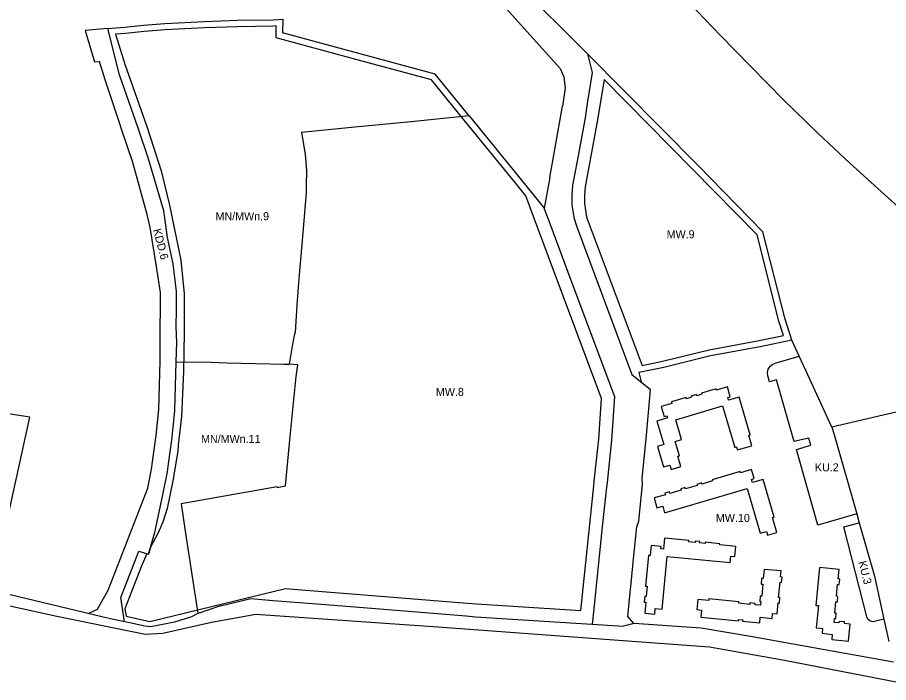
# Model space of a CAD drawing. Extents: x 7427074 to 7428708, y 5545888 to 5547145.
# Drawn here: x 7427887 to 7428431, y 5545888 to 5546303 of the extents above; entities that cross this region are included whole.
import ezdxf

# ---------------------------------------------------------------- set-up
doc = ezdxf.new("R2010")
doc.units = 0
for name, color, linetype in [('linie_rozgraniczajace', 7, 'Continuous'), ('linie_zabudowy_nieprzekraczalne', 7, 'Continuous'), ('linie_zabudowy_obowiazujace', 7, 'Continuous'), ('oznaczenia_przeznaczen', 7, 'Continuous')]:
    doc.layers.add(name, color=color, linetype=linetype)

msp = doc.modelspace()

# ---------------------------------------------------------------- linework, layer by layer
at = {"layer": 'linie_rozgraniczajace'}
for p, q in [((7428198.69, 5546324.88), (7428234.46, 5546289.38)), ((7428243.44, 5546280.38), (7428234.46, 5546289.38)), ((7428219.72, 5546203.26), (7428216.22, 5546184.01)), ((7428375.55, 5546091.63), (7428371.01, 5546101.47)), ((7428276.42, 5546077.22), (7428276.81, 5546075.47)), ((7427943.96, 5545945.48), (7427968.63, 5546009.21)), ((7427992.01, 5545982.31), (7427999.84, 5545930.84)), ((7427954.06, 5545925.65), (7427951.84, 5545940.77))]:
    msp.add_line(p, q, dxfattribs=at)
for points in [[(7428179.44, 5546322.97), (7428187.14, 5546315.01), (7428226.3, 5546271.29), (7428228.55, 5546266.02), (7428229.25, 5546260.53), (7428229.38, 5546258.91), (7428227.82, 5546247.76)], [(7428302.21, 5546317.24), (7428326.22, 5546291.96), (7428345.44, 5546272.5), (7428365.8, 5546251.69), (7428387.38, 5546230.74), (7428406.9, 5546212.4), (7428426.79, 5546194.44), (7428446.12, 5546176.98)], [(7427943.43, 5546296.21), (7427954.43, 5546297.07), (7427966.08, 5546298.37), (7427979.29, 5546299.3), (7428004, 5546300.6), (7428024.6, 5546301.36), (7428046.96, 5546301.73), (7428052.93, 5546302.11), (7428052.87, 5546293.45)], [(7427943.43, 5546296.21), (7427929.46, 5546294.91), (7427935.47, 5546275.38), (7427938.53, 5546275.65)], [(7427951.84, 5545940.77), (7427963.16, 5545969.73), (7427969.17, 5545967.91), (7427973.07, 5545981.35), (7427977.98, 5546005.07), (7427980.94, 5546019.33), (7427981.6, 5546024.25), (7427983.82, 5546040.8), (7427985.52, 5546057.69), (7427986.33, 5546088.05), (7427986.8, 5546100.02), (7427986.44, 5546109.87), (7427986.55, 5546120.63), (7427986.64, 5546131.95), (7427984.59, 5546149.32), (7427981.02, 5546165.65), (7427979.97, 5546173.44), (7427978.62, 5546182.37), (7427968.81, 5546215.51), (7427962.77, 5546233.33), (7427950.96, 5546267.28), (7427943.62, 5546296.22)], [(7428169.37, 5546241.59), (7428148.18, 5546267.75), (7428100.52, 5546280.6), (7428052.87, 5546293.45)], [(7428243.44, 5546280.38), (7428246.3, 5546268.75), (7428243.23, 5546249.44), (7428241.79, 5546240.45), (7428236.79, 5546213.29), (7428234.05, 5546198.42), (7428233.46, 5546192.08), (7428233.54, 5546186.28), (7428234.78, 5546178.28), (7428236.58, 5546172.38), (7428271.07, 5546080.15), (7428282.68, 5546070.68)], [(7428371.01, 5546101.47), (7428366.77, 5546114.59), (7428352.92, 5546169.28), (7428312.01, 5546210.98), (7428243.44, 5546280.38)], [(7427951.86, 5546234.65), (7427951.66, 5546235.37), (7427942.08, 5546264.22), (7427938.53, 5546275.65)], [(7428219.72, 5546203.26), (7428222.87, 5546220.57), (7428227.82, 5546247.76)], [(7428169.37, 5546241.59), (7428133.15, 5546237.99), (7428098.01, 5546234.53), (7428064.64, 5546231.19)], [(7428169.37, 5546241.59), (7428202.05, 5546201.42), (7428216.22, 5546184.01), (7428216.37, 5546183.63), (7428217.13, 5546181.59), (7428219.81, 5546174.4), (7428233.01, 5546139.09), (7428260.22, 5546066.34), (7428258.42, 5546039.05), (7428255.53, 5546012.65), (7428255.21, 5546009.79), (7428252.51, 5545985.06), (7428247.28, 5545933.81), (7428246.3, 5545924.24)], [(7427968.63, 5546009.21), (7427971.08, 5546021.01), (7427971.69, 5546025.58), (7427973.89, 5546041.97), (7427975.53, 5546058.32), (7427976.34, 5546088.38), (7427976.44, 5546109.74), (7427976.55, 5546120.72), (7427976.64, 5546131.4), (7427974.22, 5546147.55), (7427970.07, 5546172.02), (7427968.38, 5546180.06), (7427959.28, 5546212.48), (7427951.86, 5546234.65)], [(7428064.64, 5546231.19), (7428066.93, 5546217.81), (7428067.75, 5546207.25), (7428067.67, 5546198.47), (7428067.62, 5546193.57), (7428064.92, 5546161.29), (7428063.73, 5546147.06), (7428062.48, 5546132.17), (7428062.19, 5546128.76), (7428061.78, 5546123.8), (7428061.3, 5546116.34), (7428060.65, 5546106.55), (7428060.17, 5546104.56), (7428058.95, 5546097.79), (7428056.89, 5546086.51)], [(7428371.01, 5546101.47), (7428351.27, 5546097.43), (7428320.28, 5546091.69), (7428291.01, 5546084.56), (7428275.5, 5546081.3), (7428276.42, 5546077.22)], [(7428382.01, 5546038.8), (7428381.56, 5546040.37), (7428376.9, 5546039.28), (7428372.47, 5546038.25), (7428371.45, 5546041.83), (7428361.46, 5546076.77), (7428356.95, 5546075.54), (7428355.9, 5546079.21), (7428355.77, 5546081.37), (7428356.3, 5546083.45), (7428357.47, 5546085.27), (7428359.14, 5546086.65), (7428361.14, 5546087.43), (7428375.55, 5546091.63)], [(7428378.68, 5546084.84), (7428378.06, 5546086.19), (7428375.55, 5546091.63)], [(7427986.33, 5546088.05), (7428008.12, 5546087.74), (7428018.32, 5546087.36), (7428053.7, 5546086.48), (7428056.89, 5546086.51)], [(7428049.54, 5546009.95), (7428049.53, 5546009.52), (7428054.78, 5546010.51), (7428055.75, 5546021.52), (7428057.67, 5546041.33), (7428058.92, 5546053.92), (7428061.35, 5546078.89), (7428062.32, 5546086.07), (7428056.89, 5546086.51)], [(7428396.07, 5546047.15), (7428378.68, 5546084.84)], [(7427871.13, 5545945.16), (7427894.95, 5546053.41), (7427789.45, 5546069.63)], [(7428277.48, 5546015.35), (7428279.95, 5546039.86), (7428282.38, 5546065.7), (7428282.68, 5546070.68)], [(7428448.88, 5546059.48), (7428428.03, 5546054.73), (7428396.07, 5546047.15), (7428397.2, 5546043.21), (7428411.5, 5545993.01), (7428413.07, 5545987.5), (7428422.59, 5545954.11), (7428428.5, 5545927.32), (7428431.59, 5545913.27)], [(7428411.5, 5545993.01), (7428387.22, 5545985.95), (7428373.81, 5546033.37), (7428382.85, 5546035.92), (7428382.01, 5546038.8)], [(7428272.36, 5545924.63), (7428268.6, 5545928.98), (7428269.63, 5545939.72), (7428270.6, 5545949.75), (7428272.14, 5545965.08), (7428274.11, 5545985), (7428275.41, 5545988.56), (7428277.76, 5546011.73), (7428277.48, 5546015.35)], [(7428049.54, 5546009.95), (7427989.43, 5545999.31), (7427992.01, 5545982.31)], [(7428428.5, 5545927.32), (7428421.86, 5545925.69), (7428420.72, 5545925.77), (7428419.65, 5545926.19), (7428418.48, 5545927.24), (7428417.82, 5545928.68), (7428403.38, 5545985.04), (7428413.07, 5545987.5)], [(7428014.04, 5545935.57), (7427999.45, 5545930.71), (7427996.08, 5545928.85), (7427985.45, 5545925.51), (7427970.52, 5545922.47), (7427966.73, 5545922.97), (7427956.33, 5545925.17), (7427947.31, 5545927.07), (7427939.92, 5545928.77), (7427871.17, 5545945.15)], [(7427931.33, 5545930.82), (7427937.19, 5545933.62), (7427943.96, 5545945.48)], [(7428437.23, 5545887.71), (7428366.32, 5545901.4), (7428319.62, 5545909.88), (7428257.14, 5545914.47), (7428149.82, 5545922.39), (7428036.1, 5545930.31), (7428008.41, 5545925.26), (7427978.02, 5545918.41), (7427967.16, 5545917.77), (7427955.89, 5545920), (7427911.89, 5545928.89), (7427870.1, 5545938.24)], [(7428014.04, 5545935.57), (7428033.1, 5545940.18), (7428046.97, 5545939.06), (7428077.03, 5545936.61), (7428108.44, 5545934.2), (7428167.45, 5545929.34), (7428173.39, 5545928.81), (7428265.82, 5545923.02)], [(7428434.43, 5545900.42), (7428382.15, 5545909.84), (7428345.18, 5545916.49), (7428314.31, 5545921.73), (7428302.02, 5545922.59), (7428272.43, 5545924.65), (7428265.82, 5545923.02)]]:
    msp.add_lwpolyline(points, dxfattribs=at)
at = {"layer": 'linie_zabudowy_nieprzekraczalne'}
for p, q in [((7428198.95, 5546198.9), (7428166.26, 5546239.07)), ((7428204.78, 5546191.73), (7428198.95, 5546198.9))]:
    msp.add_line(p, q, dxfattribs=at)
for points in [[(7428048.85, 5546290.39), (7428048.9, 5546297.85), (7428047.12, 5546297.73), (7428024.71, 5546297.36), (7428004.18, 5546296.6), (7427979.54, 5546295.31), (7427966.44, 5546294.39), (7427954.81, 5546293.09), (7427948.49, 5546292.59)], [(7427948.49, 5546292.59), (7427954.34, 5546273.87), (7427968.01, 5546234.97), (7427976.94, 5546207.32), (7427982.3, 5546185.84), (7427989.32, 5546151.59), (7427991.35, 5546130.56), (7427991.5, 5546106.65), (7427990.93, 5546082.08), (7427989.68, 5546053.98), (7427987.7, 5546035.92), (7427987.38, 5546032.2), (7427984.3, 5546013.69), (7427980.72, 5545996.4), (7427978.02, 5545987.91), (7427974.87, 5545980.86), (7427970.54, 5545972.64), (7427969.17, 5545967.91), (7427968.18, 5545968.21), (7427964.59, 5545959.97), (7427954.44, 5545933.75), (7427955.1, 5545929.22), (7427969.85, 5545925.82), (7428054.77, 5545946.45), (7428077.66, 5545944.59), (7428109.07, 5545942.17), (7428168.13, 5545937.31), (7428174, 5545936.79), (7428239.14, 5545932.7), (7428247.26, 5546010.65), (7428247.58, 5546013.53), (7428250.45, 5546039.75), (7428252.12, 5546065.15), (7428212.32, 5546171.6), (7428209.64, 5546178.79), (7428204.78, 5546191.73)], [(7428166.26, 5546239.07), (7428145.89, 5546264.23), (7428099.48, 5546276.74), (7428048.85, 5546290.39)], [(7428253.7, 5546264.3), (7428249.68, 5546239.09), (7428241.98, 5546197.32), (7428241.47, 5546191.77), (7428241.53, 5546186.95), (7428242.82, 5546178.63)], [(7428365.83, 5546104.49), (7428362.92, 5546113.48), (7428349.31, 5546167.25), (7428309.16, 5546208.17), (7428253.7, 5546264.3)], [(7428242.82, 5546178.63), (7428243.24, 5546177.42), (7428277.5, 5546085.81)], [(7428277.5, 5546085.81), (7428290.13, 5546088.46), (7428319.44, 5546095.6), (7428350.5, 5546101.36), (7428365.83, 5546104.49)]]:
    msp.add_lwpolyline(points, dxfattribs=at)
at = {"layer": 'linie_zabudowy_obowiazujace'}
for points in [[(7428298.44, 5546051.74), (7428327.73, 5546060.45), (7428335.43, 5546034.57), (7428336.37, 5546034.85), (7428336.93, 5546032.99), (7428345.96, 5546035.67), (7428344.04, 5546042.13), (7428345.05, 5546042.43), (7428338.05, 5546065.97), (7428331.41, 5546063.99), (7428330.91, 5546065.67), (7428332.55, 5546066.16), (7428330.7, 5546072.36), (7428324.02, 5546070.37), (7428323.79, 5546071.15), (7428314.56, 5546068.4), (7428314.76, 5546067.75), (7428311.65, 5546066.83), (7428311.42, 5546067.59), (7428308.05, 5546066.58), (7428308.26, 5546065.87), (7428305.18, 5546064.95), (7428304.96, 5546065.67), (7428295.77, 5546062.95), (7428296.03, 5546062.09), (7428289.36, 5546060.11), (7428291.22, 5546053.85), (7428292.98, 5546054.37), (7428293.4, 5546052.97), (7428286.65, 5546050.97), (7428290.97, 5546036.38), (7428287.06, 5546035.22), (7428290.85, 5546022.42), (7428294.71, 5546023.57), (7428295.53, 5546020.78), (7428301.69, 5546022.61), (7428299.78, 5546029.07), (7428300.74, 5546029.36), (7428298.07, 5546038.36), (7428302.06, 5546039.54)], [(7428291.35, 5545993.8), (7428343.14, 5546008.9), (7428351.24, 5545981.01), (7428355.19, 5545982.15), (7428355.87, 5545979.81), (7428361.69, 5545981.5), (7428358.99, 5545990.77), (7428359.93, 5545991.05), (7428353.09, 5546014.6), (7428346.34, 5546012.65), (7428345.78, 5546014.56), (7428347.53, 5546015.07), (7428345.87, 5546020.79), (7428339, 5546018.8), (7428338.79, 5546019.53), (7428321.13, 5546014.41), (7428321.36, 5546013.62), (7428314.76, 5546011.71), (7428314.57, 5546012.36), (7428311.65, 5546011.51), (7428311.85, 5546010.81), (7428304.6, 5546008.72), (7428304.36, 5546009.55), (7428301.62, 5546008.76), (7428301.86, 5546007.93), (7428294.78, 5546005.89), (7428294.51, 5546006.81), (7428291.7, 5546006), (7428291.99, 5546005.01), (7428285.09, 5546003.02), (7428286.69, 5545996.86), (7428290.31, 5545997.8)], [(7428289.95, 5545933.52), (7428293.2, 5545966.51), (7428332.52, 5545962.64), (7428332.91, 5545966.59), (7428335.32, 5545966.35), (7428335.96, 5545972.8), (7428325.96, 5545973.79), (7428326.02, 5545974.42), (7428316.9, 5545975.32), (7428316.83, 5545974.58), (7428313.4, 5545974.92), (7428313.48, 5545975.75), (7428310.59, 5545976.04), (7428310.51, 5545975.29), (7428306.53, 5545975.69), (7428306.6, 5545976.47), (7428291.51, 5545977.98), (7428290.81, 5545970.99), (7428289.17, 5545971.15), (7428289.34, 5545972.8), (7428283.19, 5545973.41), (7428282.55, 5545967.03), (7428281.54, 5545967.13), (7428279.61, 5545948.01), (7428280.71, 5545947.9), (7428280.06, 5545941.5), (7428279.06, 5545941.6), (7428278.7, 5545937.95), (7428279.8, 5545937.83), (7428279.12, 5545931.06), (7428285.36, 5545930.43), (7428285.71, 5545933.95)], [(7428364.29, 5545957.41), (7428353.71, 5545958.42), (7428353.16, 5545952.65), (7428352.1, 5545952.75), (7428351.76, 5545949.2), (7428352.86, 5545949.09), (7428352.15, 5545941.69), (7428351.21, 5545941.78), (7428350.89, 5545938.44), (7428351.61, 5545938.37), (7428351.39, 5545935.99), (7428348.06, 5545936.31), (7428348.14, 5545937.19), (7428344.79, 5545937.5), (7428344.7, 5545936.57), (7428337.83, 5545937.23), (7428337.92, 5545938.24), (7428319.15, 5545940.03), (7428319.05, 5545939), (7428312.23, 5545939.66), (7428311.62, 5545933.28), (7428314.54, 5545933), (7428314.11, 5545928.55), (7428337.67, 5545926.3), (7428337.74, 5545927.05), (7428340.32, 5545926.81), (7428340.25, 5545926.07), (7428350.97, 5545925.05), (7428351.3, 5545928.49), (7428358.62, 5545927.79), (7428358.91, 5545930.86), (7428361.73, 5545930.59), (7428362.38, 5545937.48), (7428363.26, 5545937.39), (7428363.58, 5545940.78), (7428362.71, 5545940.86), (7428363.61, 5545950.34), (7428364.59, 5545950.24), (7428364.91, 5545953.59), (7428363.93, 5545953.68)], [(7428386.28, 5545921.86), (7428388.97, 5545921.61), (7428390.24, 5545921.5), (7428389.97, 5545918.47), (7428396.23, 5545917.66), (7428395.91, 5545914.7), (7428406.32, 5545913.62), (7428407.39, 5545924.26), (7428403.86, 5545924.64), (7428403.94, 5545925.56), (7428400.46, 5545925.85), (7428400.38, 5545925.06), (7428397.35, 5545925.32), (7428397.61, 5545927.79), (7428398.38, 5545927.72), (7428398.71, 5545931.1), (7428397.85, 5545931.15), (7428398.52, 5545938.16), (7428399.44, 5545938.11), (7428399.77, 5545941.57), (7428398.85, 5545941.62), (7428399.44, 5545948.96), (7428400.5, 5545948.86), (7428400.87, 5545952.31), (7428399.9, 5545952.42), (7428400.51, 5545958.41), (7428388.32, 5545959.54), (7428385.98, 5545935.91), (7428387.59, 5545935.76)]]:
    msp.add_lwpolyline(points, close=True, dxfattribs=at)

# ---------------------------------------------------------------- texts
at = {"layer": 'oznaczenia_przeznaczen'}
for s, p in [('MN/MWn.9', (7428010.99, 5546176.51)), ('MW.9', (7428292.8, 5546165.22)), ('MW.8', (7428148.66, 5546066.77)), ('MN/MWn.11', (7428001.95, 5546037.4)), ('KU.2', (7428385.38, 5546019.64)), ('MW.10', (7428323.56, 5545988.05))]:
    msp.add_text(s, height=5, dxfattribs=at).set_placement(p)
for s, rotation, p in [('KDD.6', 284.6351, (7427971.95, 5546170.47)), ('KU.3', 284.4671, (7428412.5, 5545962.97))]:
    msp.add_text(s, height=5, rotation=rotation, dxfattribs=at).set_placement(p)

doc.saveas('drawing.dxf')
